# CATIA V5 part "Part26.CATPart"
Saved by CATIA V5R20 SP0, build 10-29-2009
Part number: VA 100812-5
Revision: ANY
Definition: UNKNOWN
Nomenclature: VA 100812-5
Source: Unknown
Bounding box of the stored display mesh (mm): x -3.804 to 3.804, y 0.1 to 1.6, z -4 to 4
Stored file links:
  C:\Users\Utente\Desktop\IO LAVORO\3D X SITO CF\CUMSA\3D files VA\VA 121012\Part26.CATPart
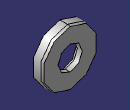
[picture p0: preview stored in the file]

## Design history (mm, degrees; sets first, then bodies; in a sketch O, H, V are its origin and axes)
Body1 "Cortar-Extruir1" (main body)
  Solid1: solid without history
